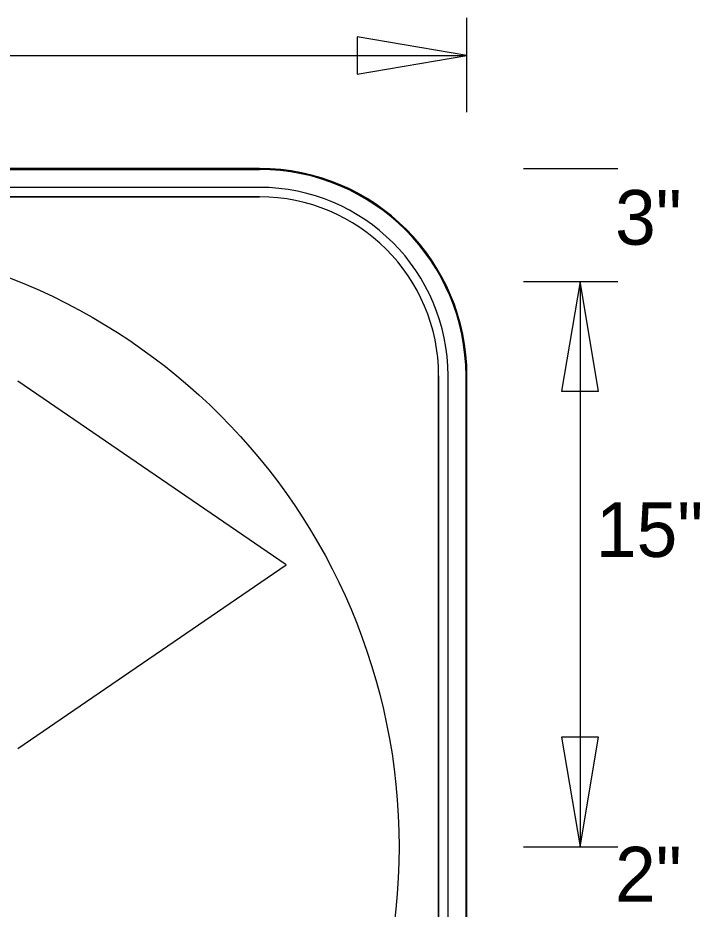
# Model space of a CAD drawing. Extents: x 0 to 770, y 0 to 495.
# Drawn here: x 703.1 to 746.7, y 420.6 to 477.6 of the extents above; entities that cross this region are included whole.
import ezdxf

# ---------------------------------------------------------------- set-up
doc = ezdxf.new("R2010")
doc.units = 0
for name, color, linetype in [('Dimension', 7, 'Continuous'), ('GSBWFill', 7, 'Continuous'), ('GSColorFill', 7, 'Continuous'), ('GSDims', 7, 'Continuous'), ('GSOutline', 7, 'Continuous'), ('IndexDetail_0', 7, 'Continuous'), ('TextStructures', 7, 'Continuous')]:
    doc.layers.add(name, color=color, linetype=linetype)

msp = doc.modelspace()

# ---------------------------------------------------------------- linework, layer by layer
at = {"layer": 'Dimension'}
for points in [[(731.79, 475.214), (724.773, 476.403), (724.773, 474.025)], [(739.024, 460.746), (737.835, 453.729), (740.213, 453.729)], [(739.024, 424.574), (740.213, 431.591), (737.835, 431.591)]]:
    msp.add_lwpolyline(points, close=True, dxfattribs=at)
at = {"layer": 'GSBWFill'}
for p, q in [((718.527, 467.98), (658.241, 467.98)), ((718.527, 466.774), (658.241, 466.774)), ((658.241, 466.171), (718.527, 466.171)), ((729.981, 454.717), (729.981, 394.431)), ((730.584, 394.431), (730.584, 454.717)), ((731.79, 394.431), (731.79, 454.717))]:
    msp.add_line(p, q, dxfattribs=at)
for radius in [13.263, 12.057, 11.454]:
    msp.add_arc((718.527, 454.717), radius, 0, 90, dxfattribs=at)
at = {"layer": 'GSColorFill'}
for p, q in [((718.527, 467.98), (658.241, 467.98)), ((718.527, 467.98), (658.241, 467.98)), ((658.241, 467.919), (718.527, 467.919)), ((718.527, 466.774), (658.241, 466.774)), ((658.241, 466.171), (718.527, 466.171)), ((729.981, 454.717), (729.981, 394.431)), ((730.584, 394.431), (730.584, 454.717)), ((731.729, 454.717), (731.729, 394.431)), ((731.79, 394.431), (731.79, 454.717)), ((731.79, 394.431), (731.79, 454.717))]:
    msp.add_line(p, q, dxfattribs=at)
for radius in [13.263, 13.263, 13.203, 12.057, 11.454]:
    msp.add_arc((718.527, 454.717), radius, 0, 90, dxfattribs=at)
at = {"layer": 'GSDims'}
for p, q in [((731.79, 471.597), (731.79, 477.625)), ((644.978, 475.214), (731.79, 475.214)), ((735.407, 467.98), (741.436, 467.98)), ((735.407, 460.746), (741.436, 460.746)), ((735.407, 460.746), (741.436, 460.746)), ((739.024, 460.746), (739.024, 424.574)), ((735.407, 424.574), (741.436, 424.574)), ((735.407, 424.574), (741.436, 424.574))]:
    msp.add_line(p, q, dxfattribs=at)
at = {"layer": 'GSOutline'}
for p, q in [((718.527, 467.98), (658.241, 467.98)), ((718.527, 466.774), (658.241, 466.774)), ((718.527, 466.171), (658.241, 466.171)), ((729.981, 394.431), (729.981, 454.717)), ((730.584, 394.431), (730.584, 454.717)), ((731.79, 394.431), (731.79, 454.717))]:
    msp.add_line(p, q, dxfattribs=at)
for radius in [13.263, 12.057, 11.454]:
    msp.add_arc((718.527, 454.717), radius, 0, 90, dxfattribs=at)
at = {"layer": 'IndexDetail_0'}
msp.add_lwpolyline([(703.068, 430.868), (720.232, 442.621), (703.068, 454.374)], dxfattribs=at)
msp.add_circle((688.384, 424.574), 39.065, dxfattribs=at)

# ---------------------------------------------------------------- texts
at = {"layer": 'TextStructures'}
for s, p in [('3"', (741.263, 463.105)), ('15"', (740.037, 443.126)), ('2"', (741.263, 421.077))]:
    msp.add_text(s, height=3.5, dxfattribs=at).set_placement(p)

doc.saveas('drawing.dxf')
